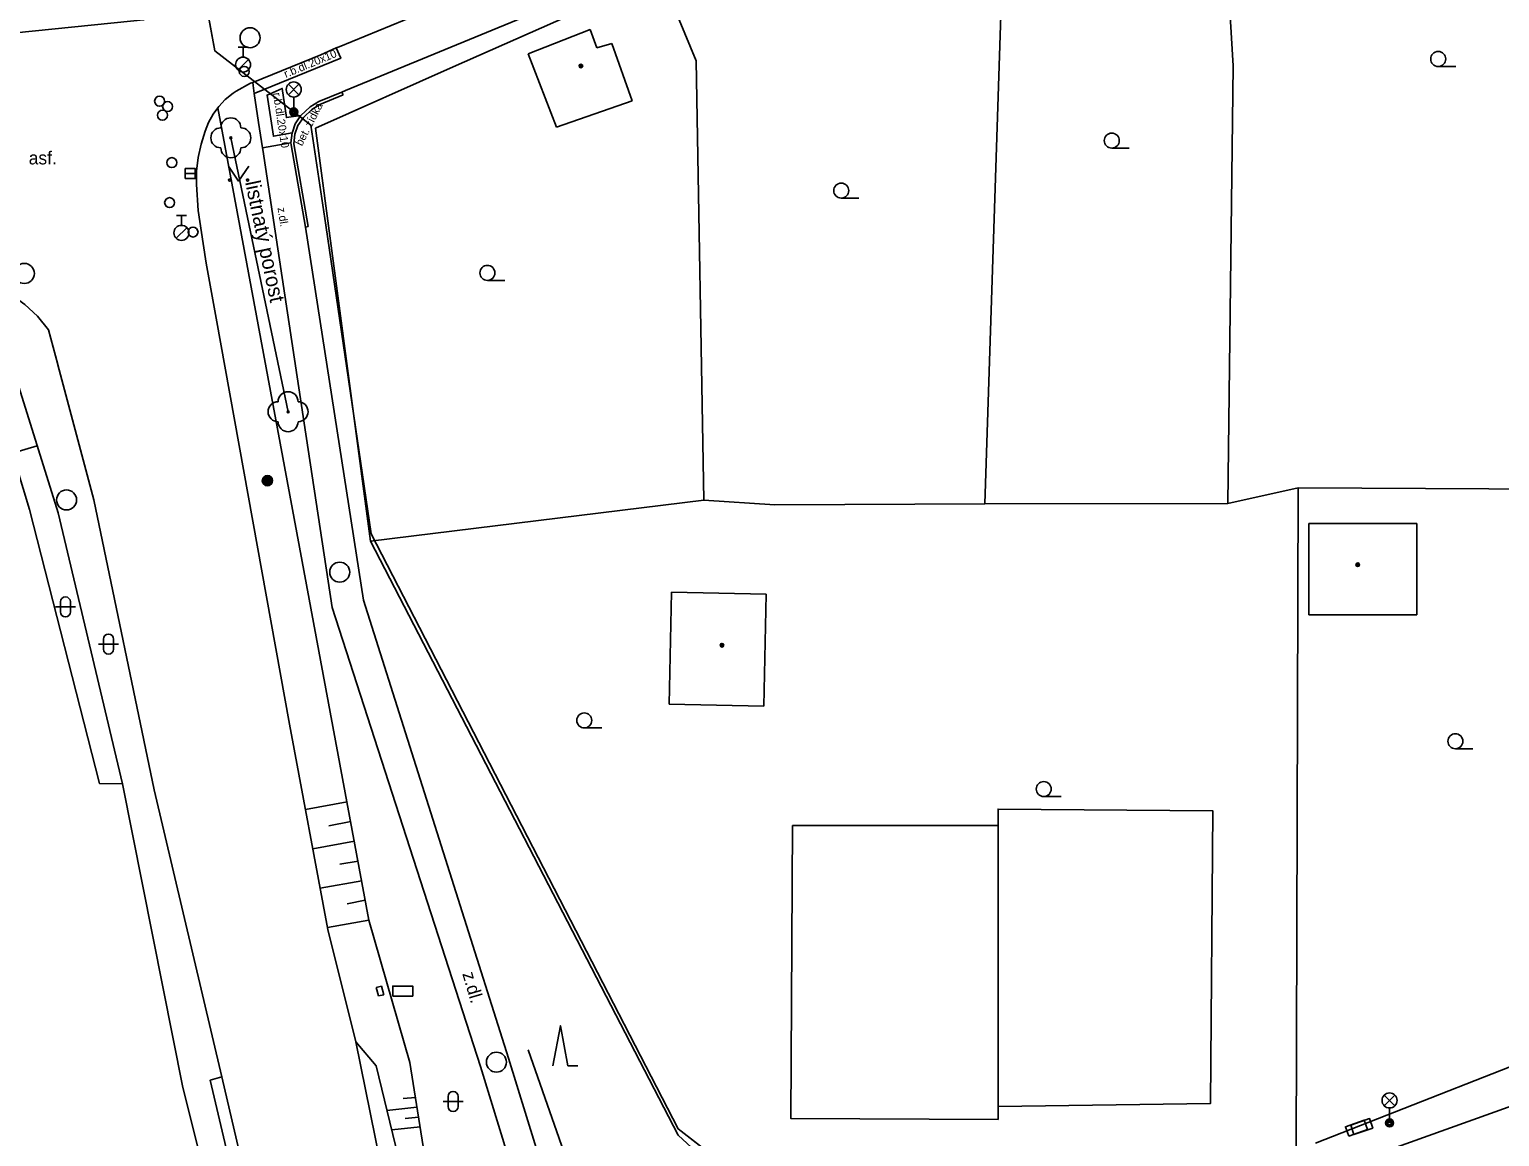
# Model space of a CAD drawing. Extents: x -598233 to -596890, y -1157848 to -1156431.
# Drawn here: x -598021.4 to -597948, y -1157132.7 to -1157077.3 of the extents above; entities that cross this region are included whole.
import ezdxf

# ---------------------------------------------------------------- set-up
doc = ezdxf.new("R2010")
doc.units = 0
for name, color, linetype in [('Level 10', 7, 'Continuous'), ('Level 11', 7, 'Continuous'), ('Level 14', 7, 'Continuous'), ('Level 15', 7, 'Continuous'), ('Level 21', 7, 'Continuous'), ('Level 22', 7, 'Continuous'), ('Level 24', 7, 'Continuous'), ('Level 25', 7, 'Continuous'), ('Level 27', 7, 'Continuous'), ('Level 28', 7, 'Continuous'), ('Level 31', 7, 'Continuous'), ('Level 33', 7, 'Continuous'), ('Level 36', 7, 'Continuous'), ('Level 39', 7, 'Continuous'), ('Level 40', 7, 'Continuous'), ('Level 42', 7, 'Continuous'), ('Level 5', 7, 'Continuous'), ('Level 7', 7, 'Continuous'), ('Vrstva 54', 7, 'Continuous'), ('Vrstva 60', 7, 'Continuous')]:
    doc.layers.add(name, color=color, linetype=linetype)

msp = doc.modelspace()

# ---------------------------------------------------------------- linework, layer by layer
at = {"layer": 'Level 10'}
for points in [[(-597981.94, -1157068.3), (-598005.96, -1157078.18)], [(-598006.88, -1157078.58), (-598010.29, -1157079.96), (-598010.4, -1157080)], [(-598006.88, -1157078.58), (-598010.29, -1157079.96), (-598010.4, -1157080)], [(-598005.96, -1157078.18), (-598006.11, -1157078.24), (-598006.88, -1157078.58)], [(-598010.4, -1157080), (-598011.12, -1157080.4)], [(-598012.66, -1157082.4), (-598012.49, -1157081.96), (-598012.26, -1157081.54), (-598012.03, -1157081.23), (-598011.98, -1157081.16), (-598011.66, -1157080.81)], [(-598011.12, -1157080.4), (-598011.27, -1157080.5), (-598011.66, -1157080.81)], [(-598013.09, -1157085.07), (-598013.09, -1157084.39), (-598013.01, -1157083.71), (-598012.87, -1157083.05), (-598012.66, -1157082.4)], [(-598013.09, -1157085.07), (-598013.01, -1157086.36)], [(-598012.76, -1157088.02), (-598013.01, -1157086.36)], [(-598012.61, -1157089), (-598012.76, -1157088.02)], [(-598005.13, -1157127.92), (-598006.53, -1157122.3), (-598008.45, -1157112.03), (-598012.12, -1157091.74), (-598012.61, -1157089)], [(-598026.59, -1157089.25), (-598025.5, -1157089.33), (-598024.62, -1157089.53), (-598023.81, -1157089.79), (-598023.15, -1157090.13), (-598022.39, -1157090.55), (-598021.68, -1157091.06), (-598021.05, -1157091.65), (-598020.49, -1157092.32)], [(-598015.21, -1157115.32), (-598018.2199, -1157100.82), (-598020.02, -1157094.07), (-598020.0231, -1157094.0683), (-598020.49, -1157092.32)], [(-598015.21, -1157115.32), (-598011.83, -1157129.66)], [(-598005.13, -1157127.92), (-598003.69, -1157135.07)], [(-598010.1, -1157137.09), (-598011.83, -1157129.66)], [(-597977.9, -1157142.07), (-597957.53, -1157134.76), (-597956.67, -1157134.45), (-597943.32, -1157129.66)]]:
    msp.add_lwpolyline(points, dxfattribs=at)
at = {"layer": 'Level 11'}
for points in [[(-597990.63, -1157074.17), (-597998.89, -1157077.58)], [(-597989.91, -1157074.57), (-597988.13, -1157078.89), (-597987.75, -1157100.84)], [(-597998.89, -1157077.58), (-598005.65, -1157080.37)], [(-598006.11, -1157078.24), (-598005.89, -1157078.75), (-598010.21, -1157080.51)], [(-598006.11, -1157078.24), (-598005.89, -1157078.75), (-598010.21, -1157080.51)], [(-597973.7, -1157101.02), (-597972.95, -1157078.11)], [(-598010.29, -1157079.96), (-598010.27, -1157080.12), (-598010.21, -1157080.51), (-598010, -1157081.96)], [(-598008.31, -1157082.48), (-598009.25, -1157082.65), (-598009.57, -1157080.59), (-598008.81, -1157080.26), (-598008.6, -1157081.72), (-598007.88, -1157081.61)], [(-598008.31, -1157082.48), (-598009.25, -1157082.65), (-598009.57, -1157080.59), (-598008.81, -1157080.26), (-598008.6, -1157081.72), (-598007.88, -1157081.61)], [(-598006.98, -1157080.91), (-598007.42, -1157081.18)], [(-598005.65, -1157080.37), (-598005.84, -1157080.45), (-598006.98, -1157080.91)], [(-598005.77, -1157080.58), (-598006.94, -1157081.07)], [(-598005.84, -1157080.45), (-598005.79, -1157080.54), (-598005.77, -1157080.58)], [(-598007.9, -1157081.63), (-598008.16, -1157082.03)], [(-598007.9, -1157081.63), (-598008.16, -1157082.03)], [(-598007.42, -1157081.18), (-598007.88, -1157081.61), (-598007.9, -1157081.63)], [(-598007.33, -1157081.31), (-598007.75, -1157081.71)], [(-598006.94, -1157081.07), (-598007.33, -1157081.31)], [(-598010, -1157081.96), (-598009.8, -1157083.23), (-598009.79, -1157083.32), (-598007.72, -1157097)], [(-598008.16, -1157082.03), (-598008.3, -1157082.44)], [(-598008.04, -1157082.11), (-598008.18, -1157082.54)], [(-598007.75, -1157081.71), (-598008.04, -1157082.11)], [(-598007.75, -1157081.71), (-598008.04, -1157082.11)], [(-598009.8, -1157083.23), (-598008.38, -1157082.98)], [(-598008.3, -1157082.44), (-598008.31, -1157082.48), (-598008.38, -1157082.98)], [(-598008.38, -1157082.98), (-598008.37, -1157083.08)], [(-598004.75, -1157105.84), (-598007.65, -1157087.2), (-598008.37, -1157083.08)], [(-598008.18, -1157082.54), (-598008.23, -1157083.03)], [(-598008.23, -1157083.03), (-598007.52, -1157087.17)], [(-598007.52, -1157087.17), (-598007.65, -1157087.2)], [(-598016.79, -1157115.02), (-598020.01, -1157101.48), (-598022.98, -1157092.03)], [(-598007.72, -1157097), (-598006.32, -1157106.21)], [(-597961.56, -1157101), (-597958.04, -1157100.2199)], [(-597958.04, -1157100.2199), (-597958.14, -1157133.38)], [(-597987.75, -1157100.84), (-598004.4, -1157102.89)], [(-597987.75, -1157100.84), (-598004.4, -1157102.89)], [(-597987.75, -1157100.84), (-597984.19, -1157101.07)], [(-597984.19, -1157101.07), (-597973.7, -1157101.02)], [(-597973.7, -1157101.02), (-597961.56, -1157101)], [(-597997.51, -1157128.73), (-598004.75, -1157105.84)], [(-598006.32, -1157106.21), (-597998.91, -1157129.14)], [(-598013.78, -1157130.19), (-598016.79, -1157115.02)], [(-597983.32, -1157117.1), (-597983.39, -1157131.75), (-597973.04, -1157131.79), (-597973.04, -1157131.14), (-597962.42, -1157130.99), (-597962.31, -1157116.37), (-597973.04, -1157116.28), (-597973.04, -1157117.1), (-597983.32, -1157117.1)], [(-597973.04, -1157117.1), (-597973.04, -1157131.14)], [(-598004.12, -1157129.12), (-598005.13, -1157127.92)], [(-597998.91, -1157129.14), (-597995.1, -1157141.52)], [(-597993.43, -1157141.96), (-597997.51, -1157128.73)], [(-598012.41, -1157129.83), (-598011.83, -1157129.66)], [(-598010.68, -1157137.2), (-598012.41, -1157129.83)]]:
    msp.add_lwpolyline(points, dxfattribs=at)
at = {"layer": 'Level 14'}
for points in [[(-598012.03, -1157081.23), (-598004.49, -1157121.83), (-598002.43, -1157128.94)], [(-598016.79, -1157115.02), (-598017.94, -1157115.01), (-598021.44, -1157101.31), (-598022.07, -1157099.21), (-598022.29, -1157098.5), (-598022.51, -1157097.78), (-598022.7199, -1157097.06), (-598022.94, -1157096.34), (-598023.15, -1157095.62), (-598023.37, -1157094.9099), (-598023.71, -1157093.78), (-598027.09, -1157092.63), (-598028.75, -1157091.89), (-598030.2199, -1157090.63)], [(-598004.12, -1157129.12), (-598002.05, -1157137.63)], [(-597995.1, -1157141.52), (-597997.85, -1157139.46), (-598000.04, -1157137.51), (-598001.44, -1157135.25), (-598002.43, -1157128.94)], [(-598008.61, -1157147.72), (-598011.09, -1157140.13), (-598012.06, -1157137.05), (-598013.78, -1157130.19)]]:
    msp.add_lwpolyline(points, dxfattribs=at)
at = {"layer": 'Level 15'}
for points in [[(-598022.29, -1157098.5), (-598021.06, -1157098.13)], [(-598005.56, -1157115.92), (-598007.65, -1157116.3)], [(-598005.38, -1157116.9099), (-598006.49, -1157117.11)], [(-598005.2, -1157117.89), (-598007.28, -1157118.27)], [(-598005.02, -1157118.88), (-598005.93, -1157119.04)], [(-598004.84, -1157119.86), (-598006.9099, -1157120.23)], [(-598004.67, -1157120.84), (-598005.57, -1157121.01)], [(-598004.49, -1157121.83), (-598006.55, -1157122.2)], [(-598002.16, -1157130.69), (-598002.77, -1157130.75)], [(-598002.08, -1157131.18), (-598003.58, -1157131.34)], [(-598001.92, -1157132.17), (-598003.34, -1157132.32)], [(-598002, -1157131.68), (-598002.67, -1157131.75)]]:
    msp.add_lwpolyline(points, dxfattribs=at)
at = {"layer": 'Level 21'}
msp.add_lwpolyline([(-597988.39, -1157138.83), (-597991.55, -1157139.3), (-597994.25, -1157134.8), (-597996.52, -1157128.31)], dxfattribs=at)
at = {"layer": 'Level 22'}
for centre in [(-598011.38, -1157082.73), (-598008.52, -1157096.42)]:
    msp.add_circle(centre, 0.05, dxfattribs=at)
for centre, start, end in [((-598011.88, -1157082.73), 90, 270), ((-598011.38, -1157082.23), 0, 180), ((-598010.88, -1157082.73), 270, 90), ((-598011.38, -1157083.23), 180, 0), ((-598008.52, -1157095.92), 0, 180), ((-598009.02, -1157096.42), 90, 270), ((-598008.02, -1157096.42), 270, 90), ((-598008.52, -1157096.92), 180, 0)]:
    msp.add_arc(centre, 0.5, start, end, dxfattribs=at)
at = {"layer": 'Level 24'}
for points in [[(-598003.85, -1157125.14), (-598004.12, -1157125.2)], [(-598004, -1157125.62), (-598004.12, -1157125.2)], [(-598003.73, -1157125.56), (-598004, -1157125.62)], [(-598003.73, -1157125.56), (-598003.85, -1157125.14)]]:
    msp.add_lwpolyline(points, dxfattribs=at)
for points in [[(-598003.29, -1157125.63), (-598002.29, -1157125.63), (-598002.29, -1157125.13), (-598003.29, -1157125.13)], [(-597955.5183, -1157132.6322), (-597954.5753, -1157132.2993), (-597954.7417, -1157131.8278), (-597955.6847, -1157132.1607)], [(-597955.2641, -1157132.5464), (-597954.3164, -1157132.2275), (-597954.4759, -1157131.7536), (-597955.4236, -1157132.0725)]]:
    msp.add_lwpolyline(points, close=True, dxfattribs=at)
at = {"layer": 'Level 25'}
for centre, radius in [((-598009.56, -1157099.87), 0.25), ((-598009.55, -1157099.86), 0.25), ((-598009.56, -1157099.87), 0.2), ((-598009.55, -1157099.86), 0.2), ((-598009.56, -1157099.87), 0.15), ((-598009.55, -1157099.86), 0.15), ((-598009.56, -1157099.87), 0.1), ((-598009.55, -1157099.86), 0.1), ((-598009.56, -1157099.87), 0.05), ((-598009.55, -1157099.86), 0.05)]:
    msp.add_circle(centre, radius, dxfattribs=at)
at = {"layer": 'Level 27'}
msp.add_line((-598013.66, -1157084.52), (-598013.16, -1157084.52), dxfattribs=at)
msp.add_lwpolyline([(-598013.66, -1157084.77), (-598013.16, -1157084.77), (-598013.16, -1157084.27), (-598013.66, -1157084.27)], close=True, dxfattribs=at)
for centre in [(-598010.42, -1157077.73), (-598021.7, -1157089.51), (-598019.59, -1157100.83), (-598005.94, -1157104.44), (-597998.11, -1157128.93)]:
    msp.add_circle(centre, 0.5, dxfattribs=at)
at = {"layer": 'Level 28'}
for p, q in [((-598011.02, -1157078.195), (-598010.52, -1157078.195)), ((-598010.77, -1157078.695), (-598010.77, -1157078.195)), ((-598011.028, -1157079.342), (-598010.498, -1157078.812)), ((-598014.1, -1157086.605), (-598013.6, -1157086.605)), ((-598013.85, -1157087.105), (-598013.85, -1157086.605)), ((-598014.108, -1157087.752), (-598013.578, -1157087.222))]:
    msp.add_line(p, q, dxfattribs=at)
for centre, radius in [((-598010.77, -1157079.07), 0.375), ((-598010.71, -1157079.41), 0.25), ((-598014.94, -1157080.9), 0.25), ((-598014.54, -1157081.17), 0.25), ((-598014.8, -1157081.6), 0.25), ((-598014.44, -1157085.97), 0.25), ((-598013.85, -1157087.48), 0.375), ((-598013.27, -1157087.44), 0.25)]:
    msp.add_circle(centre, radius, dxfattribs=at)
at = {"layer": 'Level 31'}
msp.add_circle((-598014.33, -1157083.97), 0.25, dxfattribs=at)
at = {"layer": 'Level 33'}
for p, q in [((-598008.505, -1157080.58), (-598007.975, -1157080.05)), ((-598008.505, -1157080.05), (-598007.975, -1157080.58)), ((-598008.24, -1157080.69), (-598008.24, -1157081.44)), ((-597953.745, -1157131.11), (-597953.215, -1157130.58)), ((-597953.745, -1157130.58), (-597953.215, -1157131.11)), ((-597953.48, -1157131.22), (-597953.48, -1157131.97))]:
    msp.add_line(p, q, dxfattribs=at)
for centre, radius in [((-598008.24, -1157080.315), 0.375), ((-598008.24, -1157081.44), 0.2), ((-598008.24, -1157081.44), 0.1445), ((-598008.24, -1157081.44), 0.0876), ((-597953.48, -1157130.845), 0.375), ((-597953.48, -1157131.97), 0.2), ((-597953.48, -1157131.97), 0.1445), ((-597953.48, -1157131.97), 0.0876)]:
    msp.add_circle(centre, radius, dxfattribs=at)
at = {"layer": 'Level 36'}
for p, q in [((-597951.05, -1157079.165), (-597950.175, -1157079.165)), ((-597967.36, -1157083.245), (-597966.485, -1157083.245)), ((-597980.88, -1157085.745), (-597980.005, -1157085.745)), ((-597998.56, -1157089.855), (-597997.685, -1157089.855)), ((-598020.146, -1157106.176), (-598019.146, -1157106.176)), ((-598019.896, -1157105.926), (-598019.896, -1157106.426)), ((-598019.396, -1157105.926), (-598019.396, -1157106.426)), ((-598017.996, -1157108.036), (-598016.996, -1157108.036)), ((-598017.746, -1157107.786), (-598017.746, -1157108.286)), ((-598017.246, -1157107.786), (-598017.246, -1157108.286)), ((-597993.72, -1157112.225), (-597992.845, -1157112.225)), ((-597950.19, -1157113.265), (-597949.315, -1157113.265)), ((-597970.76, -1157115.655), (-597969.885, -1157115.655)), ((-598000.526, -1157130.646), (-598000.526, -1157131.146)), ((-598000.026, -1157130.646), (-598000.026, -1157131.146)), ((-598000.776, -1157130.896), (-597999.776, -1157130.896))]:
    msp.add_line(p, q, dxfattribs=at)
for points in [[(-598011.49, -1157084.14), (-598010.99, -1157084.89), (-598010.49, -1157084.14)], [(-597995.289, -1157129.108), (-597994.914, -1157127.108), (-597994.539, -1157129.108), (-597994.039, -1157129.108)]]:
    msp.add_lwpolyline(points, dxfattribs=at)
for centre, radius in [((-597951.0501, -1157078.7899), 0.375), ((-597967.3601, -1157082.8699), 0.375), ((-598011.4402, -1157084.8398), 0.05), ((-598010.5408, -1157084.8398), 0.05), ((-597980.8801, -1157085.3699), 0.375), ((-597998.5601, -1157089.4799), 0.375), ((-597993.7201, -1157111.8499), 0.375), ((-597950.1901, -1157112.8899), 0.375), ((-597970.7601, -1157115.2799), 0.375)]:
    msp.add_circle(centre, radius, dxfattribs=at)
for centre, start, end in [((-598019.6457, -1157105.9263), 0, 180), ((-598019.6457, -1157106.4263), 180, 0), ((-598017.4957, -1157107.7863), 0, 180), ((-598017.4957, -1157108.2863), 180, 0), ((-598000.2757, -1157130.6463), 0, 180), ((-598000.2757, -1157131.1463), 180, 0)]:
    msp.add_arc(centre, 0.25, start, end, dxfattribs=at)
at = {"layer": 'Level 39'}
for centre, radius in [((-597993.89, -1157079.14), 0.09), ((-597993.89, -1157079.14), 0.0398), ((-597955.07, -1157104.07), 0.09), ((-597955.07, -1157104.07), 0.0398), ((-597986.84, -1157108.09), 0.09), ((-597986.84, -1157108.09), 0.0398)]:
    msp.add_circle(centre, radius, dxfattribs=at)
at = {"layer": 'Level 5'}
for points in [[(-597996.52, -1157078.54), (-597993.42, -1157077.32)], [(-597993.42, -1157077.32), (-597993.09, -1157078.23)], [(-597995.1, -1157082.19), (-597996.52, -1157078.54)], [(-597993.09, -1157078.23), (-597992.35, -1157078.02)], [(-597992.35, -1157078.02), (-597991.33, -1157080.88)], [(-597991.33, -1157080.88), (-597995.1, -1157082.19)], [(-597957.52, -1157102), (-597952.12, -1157102)], [(-597957.52, -1157106.57), (-597957.52, -1157102)], [(-597952.12, -1157102), (-597952.12, -1157106.57)], [(-597989.48, -1157111.03), (-597989.36, -1157105.44)], [(-597989.36, -1157105.44), (-597984.63, -1157105.54)], [(-597984.63, -1157105.54), (-597984.75, -1157111.13)], [(-597952.12, -1157106.57), (-597957.52, -1157106.57)], [(-597984.75, -1157111.13), (-597989.48, -1157111.03)]]:
    msp.add_lwpolyline(points, dxfattribs=at)
at = {"layer": 'Level 7'}
for points in [[(-597961.56, -1157101), (-597961.3, -1157079.14), (-597962.26, -1157063.06)], [(-597972.95, -1157078.11), (-597972.59, -1157067.04)], [(-597991.74, -1157075.39), (-597992.01, -1157075.51), (-598000.27, -1157079.19), (-598007.15, -1157082.25)], [(-598004.4, -1157102.89), (-598007.15, -1157082.25)], [(-598004.4, -1157102.89), (-598007.15, -1157082.25)], [(-598011.38, -1157082.73), (-598008.52, -1157096.42)], [(-597958.04, -1157100.2199), (-597942.15, -1157100.3)], [(-597989.03, -1157132.58), (-598004.4, -1157102.89)], [(-597943, -1157127.41), (-597957.18, -1157132.98)], [(-597983.04, -1157138.12), (-597989.03, -1157132.58)]]:
    msp.add_lwpolyline(points, dxfattribs=at)
at = {"layer": 'Vrstva 54'}
for p, q in [((-598012.7, -1157075.55), (-598012.18, -1157078.39)), ((-598022.29, -1157077.5), (-598016.22, -1157076.88)), ((-598012.18, -1157078.39), (-598007.76, -1157081.79)), ((-598007.76, -1157081.79), (-598007.38, -1157082.09)), ((-598007.38, -1157082.09), (-598006.64, -1157087.09)), ((-598006.64, -1157087.09), (-598004.37, -1157102.53)), ((-598004.37, -1157102.53), (-597989.03, -1157132.27)), ((-597989.03, -1157132.27), (-597984.94, -1157135.42))]:
    msp.add_line(p, q, dxfattribs=at)
at = {"layer": 'Vrstva 60'}
for points in [[(-598022.29, -1157077.5), (-598016.22, -1157076.88), (-598015.75, -1157076.83), (-598012.7, -1157075.55), (-598012.18, -1157078.39), (-598007.76, -1157081.79), (-598007.38, -1157082.09), (-598006.64, -1157087.09), (-598004.37, -1157102.53), (-597989.03, -1157132.27), (-597984.94, -1157135.42)], [(-597984.94, -1157135.42), (-597989.03, -1157132.27), (-598004.37, -1157102.53), (-598006.64, -1157087.09), (-598007.38, -1157082.09), (-598007.76, -1157081.79), (-598012.18, -1157078.39), (-598012.7, -1157075.55), (-598015.75, -1157076.83), (-598016.22, -1157076.88), (-598022.29, -1157077.5)]]:
    msp.add_lwpolyline(points, dxfattribs=at)

# ---------------------------------------------------------------- texts
at = {"layer": 'Level 40'}
for s, height, rotation, p in [('r.b.dl.20x10', 0.400002, 22.619864, (-598008.63, -1157079.74)), ('r.b.dl.20x10', 0.400002, 278.829744, (-598009.28, -1157080.5)), ('bet. zídka', 0.4, 63, (-598007.83, -1157083.17)), ('z.dl.', 0.4, 278.829744, (-598009.05, -1157086.23)), ('z.dl.', 0.65, 286.334578, (-597999.82, -1157124.51))]:
    msp.add_text(s, height=height, rotation=rotation, dxfattribs=at).set_placement(p)
msp.add_text('asf.', height=0.65, dxfattribs=at).set_placement((-598021.48, -1157084.06))
at = {"layer": 'Level 42'}
msp.add_text('listnatý porost', height=0.75, rotation=281.80004, dxfattribs=at).set_placement((-598010.67, -1157084.95))

doc.saveas('drawing.dxf')
